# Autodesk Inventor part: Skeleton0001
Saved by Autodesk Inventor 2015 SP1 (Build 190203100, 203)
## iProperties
Created: 2011-06
Part Number: Skeleton0001
Material: Steel
Description: Steel - DIN-20CrMoS4
Document SubType Name: Modeling
Designer: Guilherme Augusto Franco de Souza
Engineer: George Geraldo de Oliveia Silva
Authority: Fábio Ricardo de Oliveira Soza
Density: 7.85 g/cm^3
Appearance: Machined 02
Category: Mechanical Engineering Drawing and Design - CADD
Manager: Fábio Ricardo de Oliveira Souza
Company: SENAI - Serviço Nacional de Aprendizagem Industrial
_SkeletonDoc: Frame Skeleton File
_Version: 15.0.0
Subject: WorldSkill 2011 - London, England
Author: Guilherme Augusto Franco de Souza
Revision Number: 00
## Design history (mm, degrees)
sketch "Reference Skeleton"
body "Solid1"
